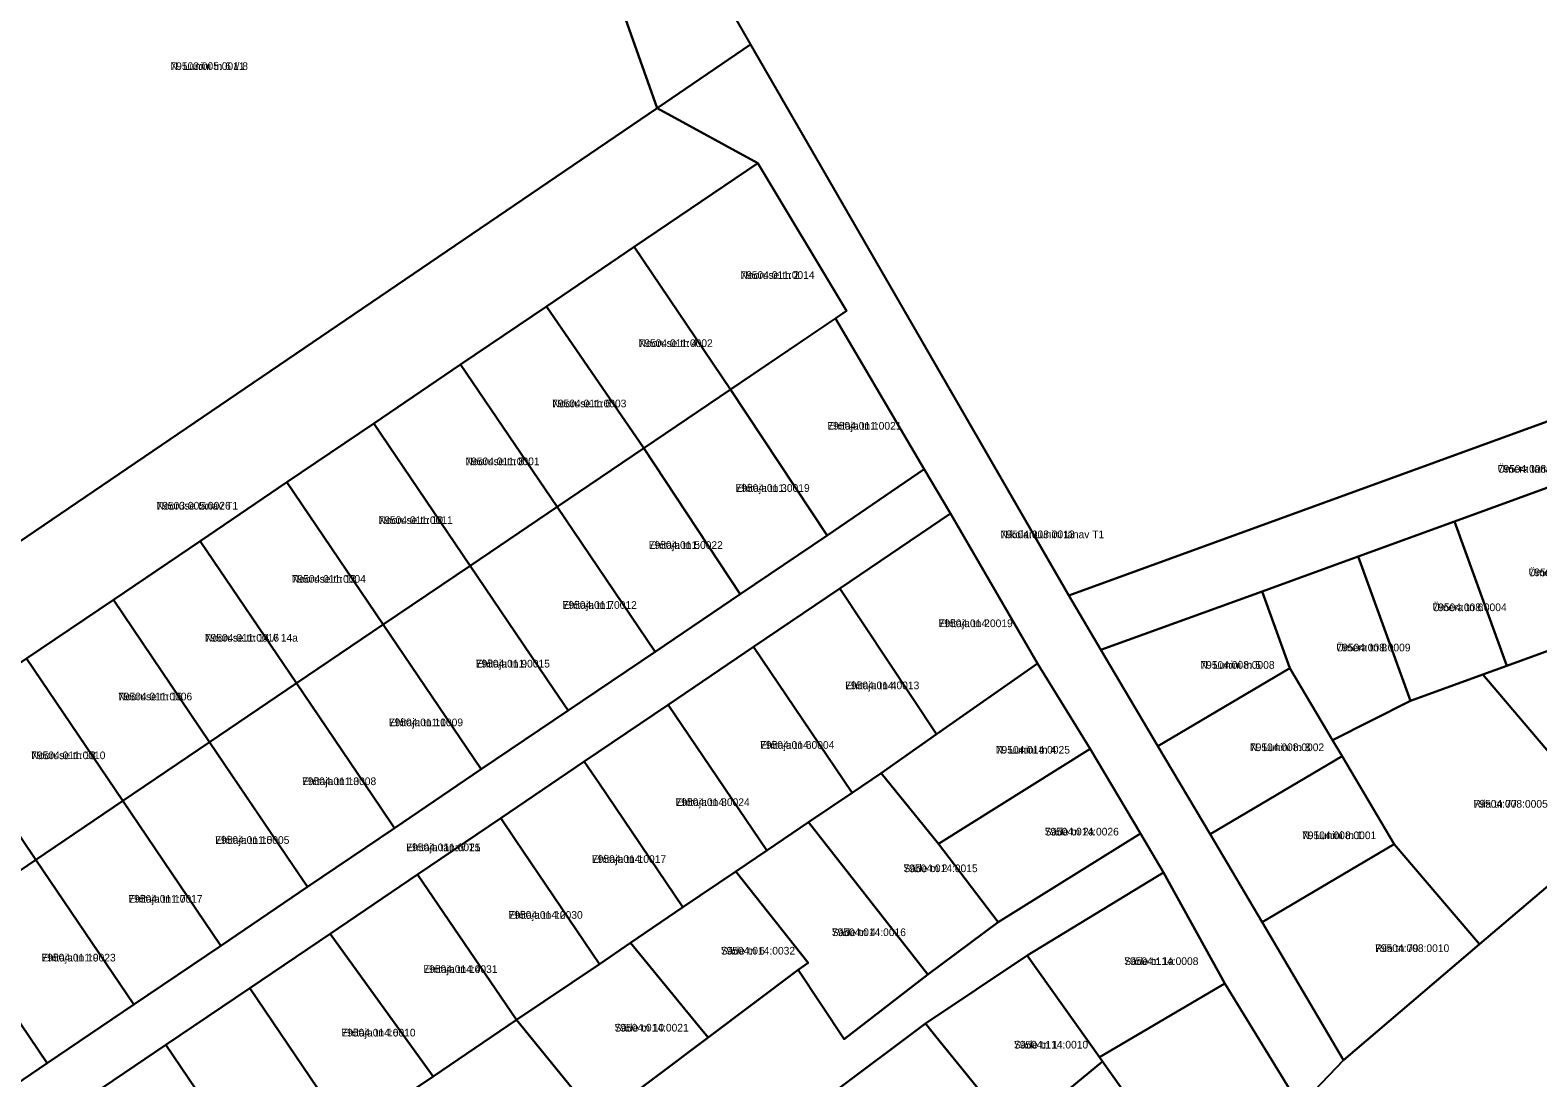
# Model space of a CAD drawing. Extents: x 643847 to 663718, y 6468443 to 6482775.
# Drawn here: x 657812.3 to 658107, y 6472629.1 to 6472833.9 of the extents above; entities that cross this region are included whole.
import ezdxf

# ---------------------------------------------------------------- set-up
doc = ezdxf.new("R2010")
doc.units = 0
for name, color, linetype in [('L_AADRESS', 7, 'Continuous'), ('PIIR', 7, 'Continuous'), ('TUNNUS', 7, 'Continuous')]:
    doc.layers.add(name, color=color, linetype=linetype)

msp = doc.modelspace()

# ---------------------------------------------------------------- linework, layer by layer
at = {"layer": 'PIIR'}
for points in [[(657934.01, 6472864.34), (657953.14, 6472831.12), (657934.87, 6472818.71), (657883.92, 6472962.53), (657862.88, 6473021.9), (657842.07, 6473084.74), (657835.57, 6473104.32), (657812.08, 6473175.21), (657784.7, 6473257.5), (657779.3, 6473272.84), (657789, 6473281.37), (657829.27, 6473158.28), (657906.99, 6472931.65), (657915.17, 6472908.01), (657922.99, 6472886.18)], [(658006.55, 6473230.36), (658097.45, 6472979.82), (658155.93, 6472821.67), (658164.93, 6472782.05), (658158.35, 6472775.44), (658015.37, 6472723.41), (657934.01, 6472864.34), (657922.99, 6472886.18), (657915.17, 6472908.01), (657932.15, 6472914.25), (657923.53, 6472937.63), (657906.99, 6472931.65), (657833.82, 6473144.96)], [(657934.87, 6472818.71), (657800.02, 6472727.08), (657744.54, 6472809.97), (657834.94, 6472871.55), (657828.28, 6472890.81), (657850.06, 6472904.99), (657839.19, 6472921.05), (657821.76, 6472909.68), (657812.07, 6472937.73), (657883.92, 6472962.53)], [(658069.07, 6472632.59), (658060.53, 6472623.66), (658045.83, 6472647.57), (658033.87, 6472669.22), (658029.33, 6472676.87), (658019.49, 6472693.41), (658009.19, 6472710.14), (657992.22, 6472739.46), (657987.04, 6472748.1), (657969.75, 6472777.58), (657971.91, 6472779.04), (657954.54, 6472807.94), (657934.87, 6472818.71), (657953.14, 6472831.12), (658015.37, 6472723.41), (658021.61, 6472712.78), (658032.76, 6472693.94), (658042.95, 6472676.73), (658053.14, 6472659.52)], [(657800.02, 6472727.08), (657934.87, 6472818.71), (657954.54, 6472807.94), (657930.37, 6472791.55), (657913.23, 6472779.94), (657896.43, 6472768.55), (657879.46, 6472757.05), (657862.49, 6472745.55), (657845.51, 6472734.05), (657828.54, 6472722.56), (657811.57, 6472711.06), (657794.59, 6472699.57), (657777.59, 6472688.09), (657760.61, 6472676.6), (657738.75, 6472661.72), (657734.13, 6472682.54)], [(657954.54, 6472807.94), (657971.91, 6472779.04), (657949.23, 6472763.69), (657930.37, 6472791.55)], [(657930.37, 6472791.55), (657949.23, 6472763.69), (657932.26, 6472752.2), (657913.23, 6472779.94)], [(658164.93, 6472782.05), (658162.54, 6472763.85), (658128.34, 6472751.5), (658109.52, 6472744.69), (658090.73, 6472737.87), (658071.92, 6472731.04), (658053.13, 6472724.22), (658021.61, 6472712.78), (658015.37, 6472723.41), (658158.35, 6472775.44)], [(657913.23, 6472779.94), (657932.26, 6472752.2), (657915.28, 6472740.71), (657896.43, 6472768.55)], [(657968.09, 6472735.14), (657949.23, 6472763.69), (657969.75, 6472777.58), (657987.04, 6472748.1)], [(657896.43, 6472768.55), (657915.28, 6472740.71), (657898.3, 6472729.23), (657879.46, 6472757.05)], [(657951.11, 6472723.66), (657932.26, 6472752.2), (657949.23, 6472763.69), (657968.09, 6472735.14)], [(657879.46, 6472757.05), (657898.3, 6472729.23), (657881.32, 6472717.74), (657862.49, 6472745.55)], [(657951.11, 6472723.66), (657934.46, 6472712.39), (657915.28, 6472740.71), (657932.26, 6472752.2)], [(657862.49, 6472745.55), (657881.32, 6472717.74), (657864.34, 6472706.25), (657845.51, 6472734.05)], [(658109.52, 6472744.69), (658119.76, 6472716.48), (658100.96, 6472709.66), (658090.73, 6472737.87)], [(657917.47, 6472700.91), (657914.66, 6472705.05), (657898.3, 6472729.23), (657915.28, 6472740.71), (657934.46, 6472712.39)], [(657992.22, 6472739.46), (658009.19, 6472710.14), (657989.5, 6472696.3), (657970.58, 6472724.79)], [(658090.73, 6472737.87), (658100.96, 6472709.66), (658096.26, 6472707.95), (658082.16, 6472702.84), (658071.92, 6472731.04)], [(657845.51, 6472734.05), (657864.34, 6472706.25), (657847.36, 6472694.75), (657828.54, 6472722.56)], [(658071.92, 6472731.04), (658082.16, 6472702.84), (658066.92, 6472695.11), (658058.57, 6472709.22), (658053.13, 6472724.22)], [(657900.48, 6472689.44), (657881.32, 6472717.74), (657898.3, 6472729.23), (657914.66, 6472705.05), (657917.47, 6472700.91)], [(657828.54, 6472722.56), (657847.36, 6472694.75), (657830.39, 6472683.26), (657811.57, 6472711.06)], [(657989.5, 6472696.3), (657978.64, 6472688.65), (657973, 6472684.85), (657953.71, 6472713.35), (657970.58, 6472724.79)], [(658053.13, 6472724.22), (658058.57, 6472709.22), (658032.76, 6472693.94), (658021.61, 6472712.78)], [(658122.04, 6472677.69), (658096.26, 6472707.95), (658100.96, 6472709.66), (658119.76, 6472716.48), (658138.81, 6472723.25), (658150.91, 6472708.93), (658154.13, 6472705.02)], [(657883.51, 6472677.94), (657880.71, 6472682.08), (657864.34, 6472706.25), (657881.32, 6472717.74), (657900.48, 6472689.44)], [(657953.71, 6472713.35), (657973, 6472684.85), (657964.47, 6472679.08), (657956.28, 6472673.53), (657937, 6472702.02)], [(657811.57, 6472711.06), (657830.39, 6472683.26), (657813.41, 6472671.76), (657794.59, 6472699.57)], [(658019.49, 6472693.41), (657989.88, 6472674.84), (657978.64, 6472688.65), (657989.5, 6472696.3), (658009.19, 6472710.14)], [(658032.76, 6472693.94), (658058.57, 6472709.22), (658066.92, 6472695.11), (658068.76, 6472692.01), (658042.95, 6472676.73)], [(658095.63, 6472655.21), (658078.95, 6472674.8), (658068.76, 6472692.01), (658066.92, 6472695.11), (658082.16, 6472702.84), (658096.26, 6472707.95), (658122.04, 6472677.69)], [(657866.52, 6472666.44), (657863.73, 6472670.58), (657847.36, 6472694.75), (657864.34, 6472706.25), (657880.71, 6472682.08), (657883.51, 6472677.94)], [(657937, 6472702.02), (657956.28, 6472673.53), (657950.22, 6472669.43), (657939.91, 6472662.47), (657923.43, 6472686.8), (657920.62, 6472690.94)], [(657794.59, 6472699.57), (657813.41, 6472671.76), (657796.42, 6472660.26), (657780.3, 6472684.07), (657777.59, 6472688.09)], [(657849.55, 6472654.94), (657830.39, 6472683.26), (657847.36, 6472694.75), (657866.52, 6472666.44)], [(658029.33, 6472676.87), (658001.56, 6472659.57), (657989.88, 6472674.84), (658019.49, 6472693.41)], [(657920.62, 6472690.94), (657923.43, 6472686.8), (657939.91, 6472662.47), (657929.68, 6472655.48), (657923.57, 6472651.36), (657907.12, 6472675.71), (657904.32, 6472679.86)], [(658068.76, 6472692.01), (658078.95, 6472674.8), (658053.14, 6472659.52), (658042.95, 6472676.73)], [(657987.78, 6472649.28), (657964.47, 6472679.08), (657973, 6472684.85), (657978.64, 6472688.65), (657989.88, 6472674.84), (658001.56, 6472659.57)], [(657832.57, 6472643.44), (657813.41, 6472671.76), (657830.39, 6472683.26), (657849.55, 6472654.94)], [(657907.12, 6472675.71), (657923.57, 6472651.36), (657907.36, 6472640.42), (657888.02, 6472668.84), (657904.32, 6472679.86)], [(657971.43, 6472636.67), (657962.46, 6472650.23), (657964.39, 6472651.59), (657950.22, 6472669.43), (657956.28, 6472673.53), (657964.47, 6472679.08), (657987.78, 6472649.28)], [(658069.07, 6472632.59), (658053.14, 6472659.52), (658078.95, 6472674.8), (658095.63, 6472655.21)], [(657832.57, 6472643.44), (657815.59, 6472631.95), (657796.42, 6472660.26), (657813.41, 6472671.76)], [(657888.02, 6472668.84), (657907.36, 6472640.42), (657891.05, 6472629.4), (657870.94, 6472657.29)], [(657964.39, 6472651.59), (657962.46, 6472650.23), (657944.82, 6472636.99), (657942.97, 6472639.25), (657929.68, 6472655.48), (657939.91, 6472662.47), (657950.22, 6472669.43)], [(658033.87, 6472669.22), (658045.83, 6472647.57), (658021.34, 6472633.12), (658007.22, 6472653)], [(657815.59, 6472631.95), (657798.61, 6472620.45), (657779.45, 6472648.77), (657796.42, 6472660.26)], [(657870.94, 6472657.29), (657891.05, 6472629.4), (657885.15, 6472625.41), (657874.42, 6472618.21), (657855.2, 6472646.64)], [(657923.31, 6472620.84), (657922.15, 6472622.27), (657907.36, 6472640.42), (657923.57, 6472651.36), (657929.68, 6472655.48), (657942.97, 6472639.25), (657944.82, 6472636.99)], [(658007.22, 6472653), (658021.34, 6472633.12), (658021.93, 6472632.29), (658004.82, 6472618.17), (657989.1, 6472637.52), (657987.31, 6472639.73)], [(657855.2, 6472646.64), (657874.42, 6472618.21), (657869.13, 6472614.57), (657858.06, 6472607.15), (657838.83, 6472635.56)], [(658060.53, 6472623.66), (658040.06, 6472606.82), (658037.32, 6472610.67), (658021.93, 6472632.29), (658021.34, 6472633.12), (658045.83, 6472647.57)], [(657905.76, 6472607.67), (657885.15, 6472625.41), (657891.05, 6472629.4), (657907.36, 6472640.42), (657922.15, 6472622.27), (657923.31, 6472620.84)], [(657987.31, 6472639.73), (657989.1, 6472637.52), (658004.82, 6472618.17), (658003.79, 6472617.3), (657987.61, 6472603.83), (657971.68, 6472623.08), (657969.15, 6472626.13)], [(657838.83, 6472635.56), (657858.06, 6472607.15), (657852.36, 6472603.25), (657841.69, 6472596.07), (657822.47, 6472624.48)], [(658023.68, 6472593.09), (658003.79, 6472617.3), (658004.82, 6472618.17), (658021.93, 6472632.29), (658037.32, 6472610.67), (658040.06, 6472606.82)]]:
    msp.add_lwpolyline(points, close=True, dxfattribs=at)
for points in [[(657798.61, 6472620.45), (657815.59, 6472631.95), (657832.57, 6472643.44), (657849.55, 6472654.94), (657866.52, 6472666.44), (657883.51, 6472677.94), (657900.48, 6472689.44), (657917.47, 6472700.91), (657934.46, 6472712.39), (657951.11, 6472723.66), (657968.09, 6472735.14), (657987.04, 6472748.1), (657992.22, 6472739.46), (657970.58, 6472724.79), (657953.71, 6472713.35), (657937, 6472702.02), (657920.62, 6472690.94), (657904.32, 6472679.86), (657888.02, 6472668.84), (657870.94, 6472657.29), (657855.2, 6472646.64), (657838.83, 6472635.56), (657822.47, 6472624.48), (657806.21, 6472613.19)], [(657910.09, 6472499.35), (657946.8, 6472530.68), (657954.75, 6472536.81), (657975.1, 6472552.5), (657991.53, 6472566.15), (658007.59, 6472579.61), (658023.68, 6472593.09), (658040.06, 6472606.82), (658060.53, 6472623.66), (658069.07, 6472632.59), (658095.63, 6472655.21), (658122.04, 6472677.69)], [(657923.31, 6472620.84), (657944.82, 6472636.99), (657962.46, 6472650.23), (657971.43, 6472636.67), (657987.78, 6472649.28), (658001.56, 6472659.57), (658029.33, 6472676.87), (658033.87, 6472669.22), (658007.22, 6472653), (657987.31, 6472639.73), (657969.15, 6472626.13)]]:
    msp.add_lwpolyline(points, dxfattribs=at)

# ---------------------------------------------------------------- texts
at = {"layer": 'L_AADRESS'}
for s, p in [('N. Lunini tn 6 // 8', (657839.7, 6472826.15)), ('Nooruse tn 2', (657951.14, 6472785.31)), ('Nooruse tn 4', (657931.23, 6472771.99)), ('Nooruse tn 6', (657914.34, 6472760.2)), ('Ehitaja tn 1', (657968.13, 6472755.83)), ('Nooruse tn 8', (657897.37, 6472748.88)), ('Ümera tänav T1', (658099.19, 6472747.42)), ('Ehitaja tn 3', (657950.18, 6472743.67)), ('Nooruse tänav T1', (657836.98, 6472740.21)), ('Nooruse tn 10', (657880.39, 6472737.39)), ('Ehitaja tn 5', (657933.2, 6472732.52)), ('Nikolai Lunini tänav T1', (658001.97, 6472734.61)), ('Ümera tn 4', (658105.24, 6472727.18)), ('Nooruse tn 12', (657863.41, 6472725.9)), ('Ehitaja tn 7', (657916.38, 6472720.8)), ('Ümera tn 6', (658086.44, 6472720.35)), ('Ehitaja tn 2', (657989.88, 6472717.22)), ('Nooruse tn 14 // 14a', (657846.44, 6472714.39)), ('Ümera tn 8', (658067.64, 6472712.48)), ('Ehitaja tn 9', (657899.39, 6472709.33)), ('N. Lunini tn 5', (658041.07, 6472709.08)), ('Nooruse tn 16', (657829.46, 6472702.91)), ('Ehitaja tn 4', (657971.61, 6472705.08)), ('Ehitaja tn 11', (657882.41, 6472697.85)), ('Nooruse tn 18', (657812.49, 6472691.41)), ('Ehitaja tn 6', (657955, 6472693.43)), ('N. Lunini tn 4', (658001.06, 6472692.49)), ('N. Lunini tn 3', (658050.76, 6472692.98)), ('Ehitaja tn 13', (657865.43, 6472686.34)), ('Ehitaja tn 8', (657938.45, 6472682.25)), ('Riia tn 77', (658094.48, 6472681.93)), ('Säde tn 2a', (658010.62, 6472676.49)), ('Ehitaja tn 15', (657848.46, 6472674.85)), ('Ehitaja tänav T1', (657885.81, 6472673.42)), ('N. Lunini tn 1', (658060.95, 6472675.77)), ('Ehitaja tn 10', (657922.11, 6472671.13)), ('Säde tn 2', (657983.02, 6472669.32)), ('Ehitaja tn 17', (657831.48, 6472663.35)), ('Ehitaja tn 12', (657905.8, 6472660.2)), ('Säde tn 4', (657969, 6472656.82)), ('Säde tn 6', (657947.32, 6472653.21)), ('Riia tn 79', (658075.22, 6472653.7)), ('Ehitaja tn 19', (657814.5, 6472651.86)), ('Ehitaja tn 14', (657889.15, 6472649.61)), ('Säde tn 1a', (658026.18, 6472651.17)), ('Säde tn 10', (657926.53, 6472638.16)), ('Ehitaja tn 16', (657873.12, 6472637.19)), ('Säde tn 1', (658004.62, 6472634.84))]:
    msp.add_text(s, height=1.5, dxfattribs=at).set_placement(p)
at = {"layer": 'TUNNUS'}
for s, p in [('79503:005:0011', (657839.7, 6472826.15)), ('79504:011:0014', (657951.14, 6472785.31)), ('79504:011:0002', (657931.23, 6472771.99)), ('79504:011:0003', (657914.34, 6472760.2)), ('79504:011:0021', (657968.13, 6472755.83)), ('79504:011:0001', (657897.37, 6472748.88)), ('79504:008:0014', (658099.19, 6472747.42)), ('79504:011:0019', (657950.18, 6472743.67)), ('79503:005:0026', (657836.98, 6472740.21)), ('79504:011:0011', (657880.39, 6472737.39)), ('79504:011:0022', (657933.2, 6472732.52)), ('79504:008:0013', (658001.97, 6472734.61)), ('79504:008:0006', (658105.24, 6472727.18)), ('79504:011:0004', (657863.41, 6472725.9)), ('79504:011:0012', (657916.38, 6472720.8)), ('79504:008:0004', (658086.44, 6472720.35)), ('79504:014:0019', (657989.88, 6472717.22)), ('79504:011:0016', (657846.44, 6472714.39)), ('79504:008:0009', (658067.64, 6472712.48)), ('79504:011:0015', (657899.39, 6472709.33)), ('79504:008:0008', (658041.07, 6472709.08)), ('79504:011:0006', (657829.46, 6472702.91)), ('79504:014:0013', (657971.61, 6472705.08)), ('79504:011:0009', (657882.41, 6472697.85)), ('79504:011:0010', (657812.49, 6472691.41)), ('79504:014:0004', (657955, 6472693.43)), ('79504:014:0025', (658001.06, 6472692.49)), ('79504:008:0002', (658050.76, 6472692.98)), ('79504:011:0008', (657865.43, 6472686.34)), ('79504:014:0024', (657938.45, 6472682.25)), ('79504:008:0005', (658094.48, 6472681.93)), ('79504:014:0026', (658010.62, 6472676.49)), ('79504:011:0005', (657848.46, 6472674.85)), ('79504:011:0025', (657885.81, 6472673.42)), ('79504:008:0001', (658060.95, 6472675.77)), ('79504:014:0017', (657922.11, 6472671.13)), ('79504:014:0015', (657983.02, 6472669.32)), ('79504:011:0017', (657831.48, 6472663.35)), ('79504:014:0030', (657905.8, 6472660.2)), ('79504:014:0016', (657969, 6472656.82)), ('79504:014:0032', (657947.32, 6472653.21)), ('79504:008:0010', (658075.22, 6472653.7)), ('79504:011:0023', (657814.5, 6472651.86)), ('79504:114:0008', (658026.18, 6472651.17)), ('79504:014:0031', (657889.15, 6472649.61)), ('79504:014:0021', (657926.53, 6472638.16)), ('79504:014:0010', (657873.12, 6472637.19)), ('79504:114:0010', (658004.62, 6472634.84))]:
    msp.add_text(s, height=1.5, dxfattribs=at).set_placement(p)

doc.saveas('drawing.dxf')
